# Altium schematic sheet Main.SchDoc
size A
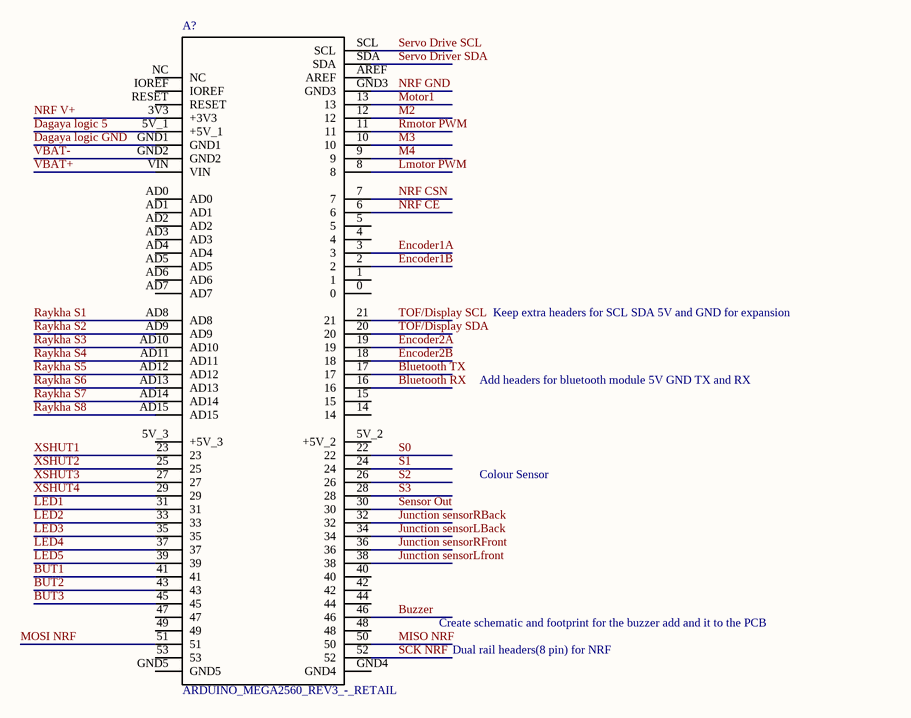
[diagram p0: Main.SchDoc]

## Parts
A?  ARDUINO_MEGA2560_REV3_-_RETAIL  [*ARDUINO_MEGA2560_REV3_-_RETAIL_ARDUINO_MEGA2560_REV3_-_RETAIL(Primary)]

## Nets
Bluetooth RX: A?.16
Bluetooth TX: A?.17
BUT1: A?.41
BUT2: A?.43
BUT3: A?.45
Buzzer: A?.46
Dagaya logic 5: A?.5V_1(+5V_1)
Dagaya logic GND: A?.GND1
Encoder1A: A?.3
Encoder1B: A?.2
Encoder2A: A?.19
Encoder2B: A?.18
Junction sensorLBack: A?.34
Junction sensorLfront: A?.38
Junction sensorRBack: A?.32
Junction sensorRFront: A?.36
LED1: A?.31
LED2: A?.33
LED3: A?.35
LED4: A?.37
LED5: A?.39
Lmotor PWM: A?.8
M2: A?.12
M3: A?.10
M4: A?.9
MISO NRF: A?.50
MOSI NRF: A?.51
Motor1: A?.13
NRF CE: A?.6
NRF CSN: A?.7
NRF GND: A?.GND3
NRF V+: A?.3V3(+3V3)
Raykha S1: A?.AD8
Raykha S2: A?.AD9
Raykha S3: A?.AD10
Raykha S4: A?.AD11
Raykha S5: A?.AD12
Raykha S6: A?.AD13
Raykha S7: A?.AD14
Raykha S8: A?.AD15
Rmotor PWM: A?.11
S0: A?.22
S1: A?.24
S2: A?.26
S3: A?.28
SCK NRF: A?.52
Sensor Out: A?.30
Servo Drive SCL: A?.SCL
Servo Driver SDA: A?.SDA
TOF/Display SCL: A?.21
TOF/Display SDA: A?.20
VBAT+: A?.VIN
VBAT-: A?.GND2
XSHUT1: A?.23
XSHUT2: A?.25
XSHUT3: A?.27
XSHUT4: A?.29

Not connected (* = marked no-connect by the designer): A? 0 1 4 5 5V_2(+5V_2) 5V_3(+5V_3) 14 15 40 42 44 47 48 49 53 AD0 AD1 AD2 AD3 AD4 AD5 AD6 AD7 AREF GND4 GND5 IOREF NC RESET

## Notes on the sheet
- Keep extra headers for SCL SDA 5V and GND for expansion
- Add headers for bluetooth module 5V GND TX and RX
- Colour Sensor
- Create schematic and footprint for the buzzer add and it to the PCB
- Dual rail headers(8 pin) for NRF

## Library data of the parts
A? = ARDUINO_MEGA2560_REV3_-_RETAIL: Dev.kit: Arduino; SPI, TWI, UART; ICSP, USB B, pin strips, supply; MP: ARDUINO MEGA2560 REV3 - RETAIL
